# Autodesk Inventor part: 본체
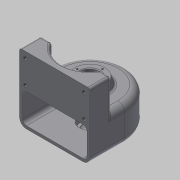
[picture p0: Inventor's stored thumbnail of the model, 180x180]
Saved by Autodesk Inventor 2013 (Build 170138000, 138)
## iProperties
Created: 2015-02
Part Number: 본체
Material: 일반
Document SubType Name: Modeling
Designer: Administrator
Density: 1 g/cm^3
Author: Administrator
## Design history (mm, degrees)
sketch "스케치1"
  geometry: L1 (50, 0)-(50, -50); L2 (50, -50)-(-50, -50); L3 (-50, -50)-(-50, 0); A1 r 50 centre (0, 0) between (50, 0) and (-50, 0); 2 further points
  constraints: 6 end point, 2 coincident, 2 point on circle, 1 centre point, 1 parallel, 1 vertical
  dimensions: "d3" = 50 distance of L1.start L1.end; "d5" = 50 radius of A1; "d6" = 100 distance of L1.end L2.end; "d7" = 50 distance from line of point (0, 0) L3; "d8" = 50 distance of L2.end L3.end
extrude "돌출1" new body sketch "스케치1" distance "d9" = 50; taper "d10" = 0 deg
feature "쉘1" dims "d30" = 4
sketch "스케치6"
  geometry: L1 (0, 60)-(0, 50); L2 (50, 50)-(0, 50) reference; L3 (0, 60)-(21.36, 60); L4 (21.36, 60)-(25, 50); 1 further point
  constraints: 6 end point, 1 coincident, 1 midpoint, 1 parallel, 1 vertical
  dimensions: "d31" = 10 distance of L1.start L1.end; "d33" = 110 deg angle of L2 L4; "d34" = 50 diameter of L4.end L1
revolve "회전3" sketch "스케치6" stored, may be unused: angle "d35" = 90 deg
sketch "스케치7"
  geometry: C1 r 21.36 at (0, 0) reference; 1 further point
  constraints: 1 coincident
hole "구멍2" sketch "스케치7" at (0, 0) diameter "d36" = 20; stored, may be unused: countersink angle "d40" = 90 deg, drill point angle "d42" = 0 deg; dims "d37" = 6, "d38" = 28, "d39" = 10, "d41" = 4
sketch "스케치8"
  geometry: C1 r 20 at (0, 0); A1 r 50 centre (0, 0) between (50, 0) and (-50, 0) reference
  constraints: 1 centre point, 1 coincident
  dimensions: "d43" = 40 diameter of C1
extrude "돌출2" join sketch "스케치8" distance "d44" = 9; taper "d45" = 0 deg
sketch "스케치9"
  geometry: A1 r 46 centre (0, 0) between (46, 0) and (-46, 0) reference; 1 further point
  constraints: 1 coincident
hole "구멍3" sketch "스케치9" at (0, 0) diameter "d46" = 20; stored, may be unused: countersink angle "d50" = 90 deg, drill point angle "d52" = 0 deg; dims "d47" = 6, "d48" = 28, "d49" = 8, "d51" = 2
sketch "스케치10"
  geometry: L1 (50, -50)-(50, 0) reference; L2 (-50, -50)-(50, -50) reference; L3 (50, -20)-(50, -50); L4 (50, -50)-(-50, -50); L5 (-50, -50)-(-50, -20); L6 (-50, -20)-(-34.641, -20); L7 (34.641, -20)-(50, -20); A1 r 50 centre (0, 0) between (50, 0) and (-50, 0) reference; A2 r 40 centre (0, 0) between (-34.641, -20) and (34.641, -20)
  constraints: 10 end point, 3 parallel, 2 horizontal, 2 perpendicular, 2 point on circle, 1 centre point, 1 coincident
  dimensions: "d53" = 30 distance of L3.start L3.end; "d55" = 100 distance of L3.end L4.end; "d56" = 0 distance between parallel lines of L2 L4; "d57" = 0 distance between parallel lines of L1 L3; "d58" = 80 diameter of A2; "d59" = 15.35898 distance of L5.end L6.end
extrude "돌출3" join sketch "스케치10" distance "d60" = 45; taper "d61" = 0 deg
sketch "스케치11" dims "d62" = 36
  geometry: L1 (0, 0)-(0, 18); C1 r 21.36 at (0, 0) reference; 1 further point
  constraints: 2 coincident, 2 end point, 1 vertical, 1 vertical alignment, 2 other
hole "구멍4" sketch "스케치11" at (0, 18) diameter "d63" = 2.459; stored, may be unused: countersink angle "d67" = 90 deg, drill point angle "d69" = 118 deg; dims "d64" = 6, "d65" = 4, "d66" = 2, "d68" = 9
sketch "스케치13"
  geometry: L1 (4, 46)-(96, 46) reference; L2 (0, 95)-(100, 95) reference; 5 further points
  dimensions: "d73" = 83.5 distance of point (8.25, 86) point (91.75, 86); "d75" = 33 distance of point (91.75, 53) point (91.75, 86); "d76" = 41.75 horizontal distance of point (50, 0) point (8.25, 53); "d77" = 41.75 horizontal distance of point (50, 0) point (8.25, 86); "d78" = 9 distance from line of point (91.75, 86) L2; "d79" = 9 distance from line of point (8.25, 86) L2; "d80" = 7 distance from line of L1 point (91.75, 53); "d81" = 7 distance from line of L1 point (8.25, 53)
hole "구멍5" sketch "스케치13" at (91.75, 86), (91.75, 53), (8.25, 53), (8.25, 86) diameter "d82" = 5.134; stored, may be unused: countersink angle "d86" = 90 deg, drill point angle "d88" = 118 deg; dims "d83" = 10, "d84" = 4, "d85" = 2, "d87" = 13
chamfer "모따기1" distance "d89" = 1; stored, may be unused: second distance "d90" = 2, angle "d91" = 45 deg
fillet "모깎기1" dims "d92" = 0.3
fillet "모깎기2" dims "d93" = 10
fillet "모깎기3" dims "d94" = 3
fillet "모깎기4" dims "d95" = 6
fillet "모깎기5" dims "d96" = 3
fillet "모깎기6" dims "d97" = 3
fillet "모깎기7" dims "d98" = 3
chamfer "모따기2" distance "d99" = 1; stored, may be unused: second distance "d100" = 2, angle "d101" = 45 deg
fillet "모깎기8" dims "d102" = 3
node "작업 평면1"
sketch "스케치14"
  geometry: 2 further points
  constraints: 1 other
  dimensions: "d103" = 25 distance of point (0, 0) point (0, 25); "d104" = 0 horizontal distance of point (0, 0) point (0, 25)
feature "엠보싱1" sketch "스케치14" dims "d105" = 0.5, "d106" = 0
node "솔리드1"
pattern_circular "원형 패턴1" dims angle "d71" = 360 deg
